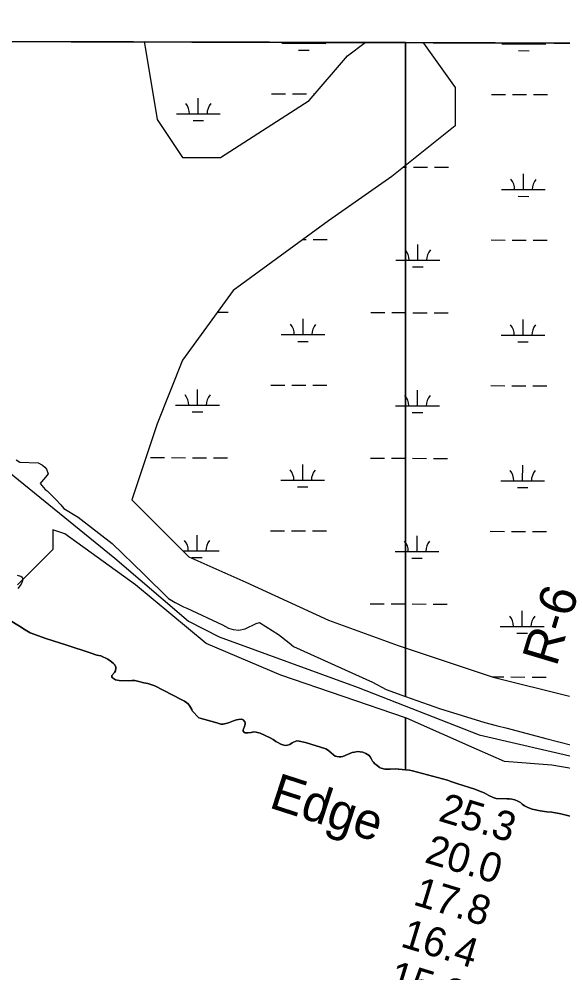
# Model space of a CAD drawing. Extents: x 3161514 to 3199414, y 831166 to 856601.
# Drawn here: x 3184362 to 3185603, y 852641 to 854820 of the extents above; entities that cross this region are included whole.
import ezdxf

# ---------------------------------------------------------------- set-up
doc = ezdxf.new("R2010")
doc.units = 0
for name, color, linetype in [('V-GRID-FRAM', 7, 'Continuous'), ('V-RIVR-IDEN', 7, 'Continuous'), ('V-RIVR-RANG', 7, 'Continuous'), ('V-RIVR-RANG-IDEN', 7, 'Continuous'), ('V-ROAD-CNTR', 7, 'Continuous'), ('V-SITE-VEGE', 7, 'Continuous'), ('V-TOPO-SHOR', 7, 'Continuous'), ('V-WETL-SWMP', 7, 'Continuous')]:
    doc.layers.add(name, color=color, linetype=linetype)

msp = doc.modelspace()

# ---------------------------------------------------------------- linework, layer by layer
at = {"layer": 'V-GRID-FRAM'}
msp.add_lwpolyline([(3165761, 854820), (3197144.3, 854733.3), (3197102, 836546.1), (3165702.9, 836632.9), (3165761, 854820)], dxfattribs=at)
at = {"layer": 'V-ROAD-CNTR'}
msp.add_lwpolyline([(3183521.7, 854763.2), (3183760.9, 854371.1), (3183900.1, 854186.1), (3184163.2, 853940.1), (3184327.8, 853794.1), (3184580.7, 853588.8), (3184748.7, 853444.5), (3184818.3, 853408.9), (3185135.6, 853293.5), (3185412.2, 853184.8), (3185648.1, 853130.5), (3185826.2, 853107.1)], dxfattribs=at)
at = {"layer": 'V-SITE-VEGE'}
for p, q in [((3185243.7, 854766.2), (3183531.5, 854770.9)), ((3193473.2, 854743.5), (3185243.7, 854766.2)), ((3185243.7, 854766.2), (3185243.7, 853272.9)), ((3185243.7, 853272.9), (3185243.7, 854766.2)), ((3184355.2, 853813.5), (3184363.9, 853808.1)), ((3184363.9, 853808.1), (3184405.3, 853806)), ((3184405.3, 853806), (3184415.2, 853801.1)), ((3184415.2, 853801.1), (3184420.5, 853796.7)), ((3184420.5, 853796.7), (3184424.4, 853791.8)), ((3184428, 853781.2), (3184422.4, 853773.9)), ((3184424.4, 853791.8), (3184428, 853781.2)), ((3184413.4, 853763.1), (3184409.8, 853759.3)), ((3184409.8, 853759.3), (3184413.6, 853754.3)), ((3184422.4, 853773.9), (3184413.4, 853763.1)), ((3184413.6, 853754.3), (3184421.6, 853745.4)), ((3184421.6, 853745.4), (3184425.7, 853742.1)), ((3184425.7, 853742.1), (3184438.3, 853730.5)), ((3184438.3, 853730.5), (3184445.9, 853722.7)), ((3184445.9, 853722.7), (3184457.2, 853710.4)), ((3184457.2, 853710.4), (3184463.8, 853702.3)), ((3184463.8, 853702.3), (3184496.7, 853682.4)), ((3184496.7, 853682.4), (3184574.6, 853622.4)), ((3184574.6, 853622.4), (3184646.4, 853552.2)), ((3184646.4, 853552.2), (3184703.2, 853496.7)), ((3184703.2, 853496.7), (3184718.5, 853487)), ((3184718.5, 853487), (3184737.1, 853477.3)), ((3184737.1, 853477.3), (3184745, 853474.2)), ((3184745, 853474.2), (3184826.1, 853436.2)), ((3184826.1, 853436.2), (3184840, 853428.6)), ((3184840, 853428.6), (3184850.4, 853426)), ((3184878.1, 853427.5), (3184902.8, 853439.4)), ((3184902.8, 853439.4), (3184910.4, 853442)), ((3184910.4, 853442), (3184954.2, 853414.5)), ((3184850.4, 853426), (3184863.7, 853424.5)), ((3184863.7, 853424.5), (3184878.1, 853427.5)), ((3184954.2, 853414.5), (3184978.2, 853395.2)), ((3184978.2, 853395.2), (3184987.9, 853387.1)), ((3184987.9, 853387.1), (3185168.2, 853305.3)), ((3185168.2, 853305.3), (3185199.8, 853288.4)), ((3185199.8, 853288.4), (3185243.7, 853272.9)), ((3185243.7, 853272.9), (3185321.6, 853245.3)), ((3185321.6, 853245.3), (3185424.6, 853213.2)), ((3185245.7, 853223), (3185243.7, 853223.7)), ((3185243.7, 853223.7), (3185243.7, 853105.2)), ((3185407, 853151.2), (3185245.7, 853223)), ((3185424.6, 853213.2), (3185450.9, 853206.1)), ((3185450.9, 853206.1), (3185475.5, 853200.5)), ((3185475.5, 853200.5), (3185563.7, 853176.5)), ((3185563.7, 853176.5), (3185654.5, 853153.4)), ((3185469.7, 853124.3), (3185407, 853151.2)), ((3185577.3, 853115.4), (3185469.7, 853124.3)), ((3185243.7, 853105.2), (3185252.7, 853104.4)), ((3185252.7, 853104.4), (3185259.4, 853102.9)), ((3185259.4, 853102.9), (3185339.5, 853081.3)), ((3185684.8, 853097.4), (3185577.3, 853115.4)), ((3185339.5, 853081.3), (3185347.2, 853078.6)), ((3185347.2, 853078.6), (3185363, 853072.9)), ((3185363, 853072.9), (3185401.9, 853060.8)), ((3185401.9, 853060.8), (3185411.3, 853057.5)), ((3185411.3, 853057.5), (3185422.9, 853052.6)), ((3185422.9, 853052.6), (3185434, 853046.4)), ((3185434, 853046.4), (3185443.4, 853042)), ((3185443.4, 853042), (3185450.9, 853040)), ((3185450.9, 853040), (3185474.7, 853038.9)), ((3185474.7, 853038.9), (3185481.3, 853038.8)), ((3185481.3, 853038.8), (3185486.3, 853038)), ((3185486.3, 853038), (3185493.4, 853036.2)), ((3185493.4, 853036.2), (3185499.9, 853033.5)), ((3185499.9, 853033.5), (3185505.9, 853030.4)), ((3185505.9, 853030.4), (3185510.3, 853027)), ((3185510.3, 853027), (3185515.4, 853022.5)), ((3185515.4, 853022.5), (3185523.1, 853018.9)), ((3185523.1, 853018.9), (3185532.7, 853015.5)), ((3185532.7, 853015.5), (3185551.4, 853011.5)), ((3185551.4, 853011.5), (3185566.1, 853009.5)), ((3185566.1, 853009.5), (3185577.8, 853008.5)), ((3185577.8, 853008.5), (3185598, 853004.8)), ((3185598, 853004.8), (3185625.8, 852997.9))]:
    msp.add_line(p, q, dxfattribs=at)
for points in [[(3185243.7, 853105.2), (3185243.7, 853223.7), (3184959, 853321.6), (3184788.7, 853393.4), (3184627.4, 853527.9), (3184466.2, 853644.4), (3184439.3, 853653.4), (3184439.3, 853608.6), (3184358.6, 853527.9)], [(3184342, 853446.3), (3184362.6, 853433.6), (3184375.5, 853424.6), (3184387.2, 853418.4), (3184423.1, 853405.2), (3184470.9, 853389.7), (3184524.3, 853372), (3184539.3, 853367.3), (3184548.2, 853365.7), (3184564.5, 853357.8), (3184573.1, 853351.9), (3184577.6, 853348.3), (3184580.7, 853344.8), (3184582.6, 853339.7), (3184582.8, 853337.1), (3184581.7, 853331.1), (3184579.6, 853327.2), (3184573.9, 853320.9), (3184573.8, 853317.5), (3184575.3, 853315.4), (3184577.3, 853313.4), (3184582.1, 853311), (3184590.1, 853309.1), (3184610.8, 853308.4), (3184619.5, 853309.3), (3184626.2, 853309.1), (3184635, 853306.7), (3184646.5, 853304), (3184656, 853302), (3184671.4, 853297), (3184732.2, 853265.6), (3184739.5, 853261.6), (3184744.9, 853258.4), (3184748, 853255.8), (3184752, 853250.9), (3184755.9, 853243.3), (3184757.1, 853240.1), (3184772.5, 853223.8), (3184813.5, 853212.4), (3184822, 853209.4), (3184824.4, 853209.2), (3184827.8, 853209.4), (3184839.8, 853212.6), (3184851.3, 853217.3), (3184858, 853219.3), (3184862.5, 853220.4), (3184868.7, 853221), (3184872, 853220), (3184873.7, 853219.2), (3184877.1, 853214.9), (3184877.9, 853213.2), (3184878, 853209.1), (3184875.8, 853201.5), (3184874.3, 853198.4), (3184873.3, 853195.4), (3184873.5, 853192.8), (3184874.2, 853191.7), (3184878.1, 853189.7), (3184884.2, 853189.5), (3184891.3, 853190.2), (3184894.6, 853191.2), (3184897.7, 853191.7), (3184902.9, 853191.5), (3184911.9, 853188.7), (3184934.6, 853178.4), (3184941.8, 853174.2), (3184948, 853170.1), (3184952.6, 853167.3), (3184959.6, 853163.8), (3184965.9, 853161.6), (3184970.3, 853161)], [(3184970.3, 853161), (3184974.7, 853161.1), (3184980.1, 853163.1), (3184985.5, 853166.7), (3184988.1, 853168.2), (3184995.9, 853171.2), (3185001.2, 853170.4), (3185015.8, 853167.4), (3185061.6, 853152.9), (3185065.7, 853151.1), (3185068.7, 853148.7), (3185079.8, 853139), (3185083.4, 853136.6), (3185087.1, 853135.5), (3185092.1, 853134.8), (3185096.5, 853134.7), (3185100.8, 853135.7), (3185122.4, 853144.4), (3185127.7, 853145.8), (3185134.2, 853146.8), (3185140.5, 853146.4), (3185146.4, 853145.4), (3185153.2, 853142.7), (3185157.4, 853140.4), (3185160.6, 853138.2), (3185163.4, 853134.5), (3185166.3, 853129.7), (3185168.7, 853125), (3185170.4, 853122.4), (3185174, 853118.8), (3185178, 853115.4), (3185184.3, 853110.7), (3185188.5, 853108.7), (3185196.9, 853107), (3185201.3, 853106.6), (3185208.8, 853107), (3185220.5, 853107.3), (3185243.7, 853105.2)]]:
    msp.add_lwpolyline(points, dxfattribs=at)
at = {"layer": 'V-TOPO-SHOR'}
for points in [[(3184359.7, 853519.1), (3184364.9, 853526.3), (3184368.6, 853531.8), (3184370.6, 853537.3), (3184370.5, 853542.8), (3184369.1, 853544.6), (3184366.1, 853546.4), (3184358.3, 853548.7)], [(3184752, 853250.9), (3184748, 853255.8), (3184744.9, 853258.4), (3184739.5, 853261.6), (3184732.2, 853265.6), (3184671.4, 853297), (3184656, 853302), (3184646.5, 853304), (3184635, 853306.7), (3184626.2, 853309.1), (3184619.5, 853309.3), (3184610.8, 853308.4), (3184590.1, 853309.1), (3184582.1, 853311), (3184577.3, 853313.4), (3184575.3, 853315.4), (3184573.8, 853317.5), (3184573.9, 853320.9), (3184579.6, 853327.2), (3184581.7, 853331.1), (3184582.8, 853337.1), (3184582.6, 853339.7), (3184580.7, 853344.8), (3184577.6, 853348.3), (3184573.1, 853351.9), (3184564.5, 853357.8), (3184548.2, 853365.7), (3184539.3, 853367.3), (3184524.3, 853372), (3184470.9, 853389.7), (3184423.1, 853405.2), (3184387.2, 853418.4), (3184375.5, 853424.6), (3184362.6, 853433.6), (3184342, 853446.3)], [(3185625.8, 852997.9), (3185598, 853004.8), (3185577.8, 853008.5), (3185566.1, 853009.5), (3185551.4, 853011.5), (3185532.7, 853015.5), (3185523.1, 853018.9), (3185515.4, 853022.5), (3185510.3, 853027), (3185505.9, 853030.4), (3185499.9, 853033.5), (3185493.4, 853036.2), (3185486.3, 853038), (3185481.3, 853038.8), (3185474.7, 853038.9), (3185450.9, 853040), (3185443.4, 853042), (3185434, 853046.4), (3185422.9, 853052.6), (3185411.3, 853057.5), (3185401.9, 853060.8), (3185363, 853072.9), (3185347.2, 853078.6), (3185339.5, 853081.3), (3185259.4, 853102.9), (3185252.7, 853104.4), (3185220.5, 853107.3), (3185208.8, 853107), (3185201.3, 853106.6), (3185196.9, 853107), (3185188.5, 853108.7), (3185184.3, 853110.7), (3185178, 853115.4), (3185174, 853118.8), (3185170.4, 853122.4), (3185168.7, 853125), (3185166.3, 853129.7), (3185163.4, 853134.5), (3185160.6, 853138.2), (3185157.4, 853140.4), (3185153.2, 853142.7), (3185146.4, 853145.4), (3185140.5, 853146.4), (3185134.2, 853146.8), (3185127.7, 853145.8), (3185122.4, 853144.4), (3185100.8, 853135.7), (3185096.5, 853134.7), (3185092.1, 853134.8), (3185087.1, 853135.5), (3185083.4, 853136.6), (3185079.8, 853139), (3185068.7, 853148.7), (3185065.7, 853151.1), (3185061.6, 853152.9), (3185015.8, 853167.4), (3185001.2, 853170.4), (3184995.9, 853171.2), (3184988.1, 853168.2), (3184985.5, 853166.7), (3184980.1, 853163.1), (3184974.7, 853161.1), (3184970.3, 853161), (3184965.9, 853161.6), (3184959.6, 853163.8), (3184952.6, 853167.3), (3184948, 853170.1), (3184941.8, 853174.2), (3184934.6, 853178.4), (3184911.9, 853188.7), (3184902.9, 853191.5), (3184897.7, 853191.7), (3184894.6, 853191.2), (3184891.3, 853190.2), (3184884.2, 853189.5), (3184878.1, 853189.7), (3184874.2, 853191.7), (3184873.5, 853192.8), (3184873.3, 853195.4), (3184874.3, 853198.4), (3184875.8, 853201.5), (3184878, 853209.1), (3184877.9, 853213.2), (3184877.1, 853214.9), (3184873.7, 853219.2), (3184872, 853220), (3184868.7, 853221), (3184862.5, 853220.4), (3184858, 853219.3), (3184851.3, 853217.3), (3184839.8, 853212.6), (3184827.8, 853209.4), (3184824.4, 853209.2), (3184822, 853209.4), (3184813.5, 853212.4), (3184772.5, 853223.8), (3184757.1, 853240.1), (3184755.9, 853243.3), (3184752, 853250.9)]]:
    msp.add_lwpolyline(points, dxfattribs=at)
at = {"layer": 'V-WETL-SWMP'}
for p, q in [((3185152, 854766.4), (3184647.8, 854767.8)), ((3184647.8, 854767.8), (3184648.1, 854764.7)), ((3184648.1, 854764.7), (3184677, 854591)), ((3184961.9, 854764.8), (3185061.9, 854764.5)), ((3185011.9, 854764.6), (3185011.9, 854766.8)), ((3185111.1, 854735.8), (3185152, 854766.4)), ((3186890.4, 854761.6), (3185283.4, 854766.1)), ((3185283.4, 854766.1), (3185284.8, 854764.7)), ((3185284.8, 854764.7), (3185357.1, 854663.4)), ((3185463.8, 854763.4), (3185563.8, 854763.1)), ((3185513.8, 854763.3), (3185513.8, 854765.4)), ((3184999.8, 854749.2), (3185023.8, 854749.2)), ((3185024.3, 854634.4), (3185111.1, 854735.8)), ((3185501.7, 854747.9), (3185525.7, 854747.8)), ((3184938.1, 854649.4), (3184970.1, 854649.3)), ((3184986.1, 854649.3), (3185018.1, 854649.2)), ((3185034.1, 854649.1), (3185036.9, 854649.1)), ((3185357.1, 854663.4), (3185357.1, 854576.5)), ((3184770.9, 854603.4), (3184771, 854639.4)), ((3184821.7, 854504.1), (3185024.3, 854634.4)), ((3185440, 854648), (3185472, 854647.9)), ((3185488, 854647.9), (3185520, 854647.8)), ((3185536, 854647.8), (3185568, 854647.7)), ((3184677, 854591), (3184734.9, 854504.1)), ((3184720.9, 854603.6), (3184820.9, 854603.3)), ((3184758.9, 854588), (3184782.9, 854588)), ((3185357.1, 854576.5), (3185212.4, 854460.6)), ((3184734.9, 854504.1), (3184821.7, 854504.1)), ((3185239.2, 854482.1), (3185245.7, 854482.1)), ((3185261.7, 854482), (3185293.7, 854481.9)), ((3185309.7, 854481.9), (3185341.7, 854481.8)), ((3185212.4, 854460.6), (3185067.7, 854359.2)), ((3185512.8, 854430.6), (3185512.9, 854466.6)), ((3185462.8, 854430.7), (3185562.8, 854430.4)), ((3185500.8, 854415.2), (3185524.8, 854415.1)), ((3185067.7, 854359.2), (3184850.6, 854199.9)), ((3185009.5, 854316.5), (3185017.2, 854316.5)), ((3185033.2, 854316.5), (3185065.2, 854316.4)), ((3185271.9, 854269.4), (3185272, 854305.4)), ((3185439.1, 854315.4), (3185471.1, 854315.3)), ((3185487.1, 854315.2), (3185519.1, 854315.1)), ((3185535.1, 854315.1), (3185567.1, 854315)), ((3185221.9, 854269.5), (3185321.9, 854269.2)), ((3185259.9, 854254), (3185283.9, 854253.9)), ((3184850.6, 854199.9), (3184734.9, 854040.6)), ((3184814.8, 854150.6), (3184838.8, 854150.5)), ((3185164.8, 854149.6), (3185196.8, 854149.5)), ((3185212.8, 854149.5), (3185244.8, 854149.4)), ((3185260.8, 854149.3), (3185292.8, 854149.3)), ((3185308.8, 854149.2), (3185340.8, 854149.1)), ((3185010, 854099.3), (3185010.1, 854135.3)), ((3185511.9, 854097.9), (3185512, 854133.9)), ((3184960, 854099.4), (3185060, 854099.2)), ((3184998, 854083.9), (3185022, 854083.8)), ((3185461.9, 854098), (3185561.9, 854097.8)), ((3185499.9, 854082.5), (3185523.9, 854082.4)), ((3184734.9, 854040.6), (3184677, 853895.8)), ((3184769.1, 853938.1), (3184769.2, 853974.1)), ((3184936.3, 853984.1), (3184968.3, 853984)), ((3184984.3, 853983.9), (3185016.3, 853983.8)), ((3185032.3, 853983.8), (3185064.3, 853983.7)), ((3185438.2, 853982.7), (3185470.2, 853982.6)), ((3185486.2, 853982.5), (3185518.2, 853982.5)), ((3185534.2, 853982.4), (3185566.2, 853982.3)), ((3185271, 853936.7), (3185271.1, 853972.7)), ((3184719.1, 853938.2), (3184819.1, 853938)), ((3185221, 853936.8), (3185321, 853936.6)), ((3184757.1, 853922.7), (3184781.1, 853922.6)), ((3185259, 853921.3), (3185283, 853921.2)), ((3184677, 853895.8), (3184619.1, 853722)), ((3184661.9, 853818.3), (3184693.9, 853818.2)), ((3184709.9, 853818.2), (3184741.9, 853818.1)), ((3184757.9, 853818.1), (3184789.9, 853818)), ((3184805.9, 853817.9), (3184837.9, 853817.8)), ((3185009.1, 853766.6), (3185009.2, 853802.6)), ((3185163.8, 853816.9), (3185195.8, 853816.8)), ((3185211.8, 853816.8), (3185243.8, 853816.7)), ((3185259.8, 853816.7), (3185291.8, 853816.6)), ((3185307.8, 853816.5), (3185339.8, 853816.4)), ((3185511, 853765.2), (3185511.1, 853801.2)), ((3184959.1, 853766.8), (3185059.1, 853766.5)), ((3185461, 853765.4), (3185561, 853765.1)), ((3184997.1, 853751.2), (3185021.1, 853751.2)), ((3185499, 853749.8), (3185523, 853749.8)), ((3184619.1, 853722), (3184749.3, 853591.7)), ((3184935.4, 853651.4), (3184967.4, 853651.3)), ((3184983.4, 853651.3), (3185015.4, 853651.2)), ((3185031.4, 853651.1), (3185063.4, 853651)), ((3185437.3, 853650), (3185469.3, 853649.9)), ((3185485.3, 853649.9), (3185517.3, 853649.8)), ((3185533.3, 853649.7), (3185565.3, 853649.6)), ((3184768.2, 853605.4), (3184768.3, 853641.4)), ((3185270.1, 853604), (3185270.2, 853640)), ((3184735.6, 853605.5), (3184818.2, 853605.3)), ((3185220.1, 853604.2), (3185320.1, 853603.9)), ((3184749.3, 853591.7), (3184879.6, 853533.8)), ((3184756.1, 853590), (3184780.1, 853590)), ((3185258, 853588.6), (3185282, 853588.6)), ((3184879.6, 853533.8), (3185067.7, 853446.9)), ((3185162.9, 853484.3), (3185194.9, 853484.2)), ((3185210.9, 853484.1), (3185242.9, 853484)), ((3185258.9, 853484), (3185290.9, 853483.9)), ((3185306.9, 853483.9), (3185338.9, 853483.8)), ((3185510.1, 853432.6), (3185510.2, 853468.6)), ((3185067.7, 853446.9), (3185226.9, 853389)), ((3185460.1, 853432.7), (3185560.1, 853432.4)), ((3185498, 853417.2), (3185522, 853417.1)), ((3185226.9, 853389), (3185443.9, 853316.6)), ((3185441.7, 853317.3), (3185468.4, 853317.2)), ((3185443.9, 853316.6), (3185617.6, 853273.1)), ((3185484.4, 853317.2), (3185516.4, 853317.1)), ((3185532.4, 853317.1), (3185564.4, 853317))]:
    msp.add_line(p, q, dxfattribs=at)
for centre, start, end in [((3184956.6, 854765.3), 359.0699, 2.6376), ((3185067.1, 854765), 177.0459, 180.6135), ((3185458.5, 854763.9), 359.0699, 2.637), ((3185569, 854763.6), 177.0465, 180.6135), ((3184715.7, 854604.1), 359.0699, 40.6135), ((3184826.2, 854603.8), 139.0699, 180.6135), ((3185457.6, 854431.2), 359.0699, 40.6135), ((3185568.1, 854430.9), 139.0699, 180.6135), ((3185216.7, 854270), 359.0699, 40.6135), ((3185327.2, 854269.7), 139.0699, 180.6135), ((3184954.8, 854099.9), 359.0699, 40.6135), ((3185065.3, 854099.6), 139.0699, 180.6135), ((3185456.7, 854098.5), 359.0699, 40.6135), ((3185567.2, 854098.2), 139.0699, 180.6135), ((3184713.9, 853938.7), 359.0699, 40.6135), ((3184824.3, 853938.4), 139.0699, 180.6135), ((3185215.8, 853937.3), 359.0699, 40.6135), ((3185326.3, 853937), 139.0699, 180.6135), ((3184953.9, 853767.2), 359.0699, 40.6135), ((3185064.3, 853766.9), 139.0699, 180.6135), ((3185455.8, 853765.9), 359.0699, 40.6135), ((3185566.3, 853765.6), 139.0699, 180.6135), ((3184712.9, 853606), 359.0699, 40.6135), ((3184823.4, 853605.7), 139.0699, 180.6135), ((3185214.9, 853604.7), 359.0699, 40.6135), ((3185325.3, 853604.4), 139.0699, 180.6135), ((3185454.9, 853433.2), 359.0699, 40.6135), ((3185565.3, 853432.9), 139.0699, 180.6135)]:
    msp.add_arc(centre, 35.2, start, end, dxfattribs=at)

# ---------------------------------------------------------------- texts
at = {"layer": 'V-RIVR-IDEN'}
msp.add_text('Edge', height=83, rotation=342.0664, dxfattribs=at).set_placement((3184929.8, 853019.8))
at = {"layer": 'V-RIVR-RANG'}
for s, p in [('25.3', (3185316.2, 852989.5)), ('20.0', (3185284.7, 852894.6)), ('17.8', (3185258.7, 852797.9)), ('16.4', (3185229.9, 852702.2)), ('15.2', (3185201.2, 852606.4))]:
    msp.add_text(s, height=67, rotation=343.1483, dxfattribs=at).set_placement(p)
at = {"layer": 'V-RIVR-RANG-IDEN'}
msp.add_text('R-6', height=83, rotation=73.2939, dxfattribs=at).set_placement((3185588.2, 853339))

doc.saveas('drawing.dxf')
